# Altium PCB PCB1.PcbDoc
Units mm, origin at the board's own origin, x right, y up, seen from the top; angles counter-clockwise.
Board outline 13.84 x 13.84 mm, 2 copper layers (Top Layer, Bottom Layer); 7 components, 5 nets, 26 pads, 3 vias.
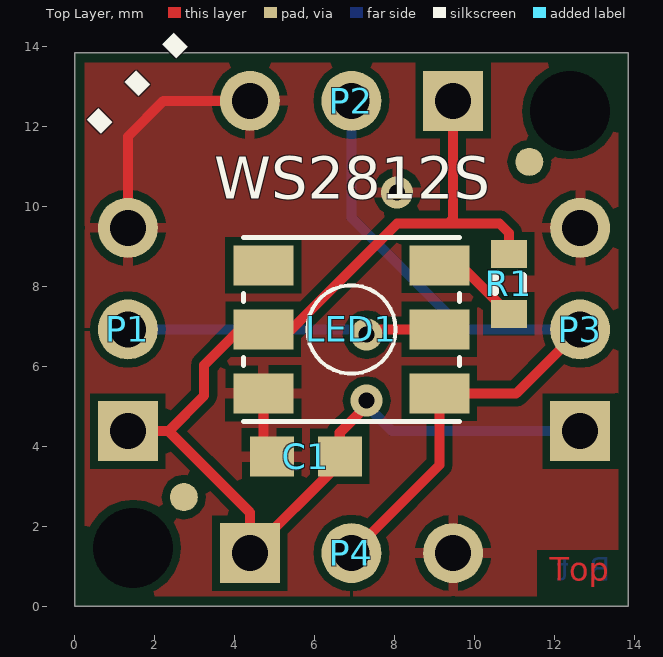
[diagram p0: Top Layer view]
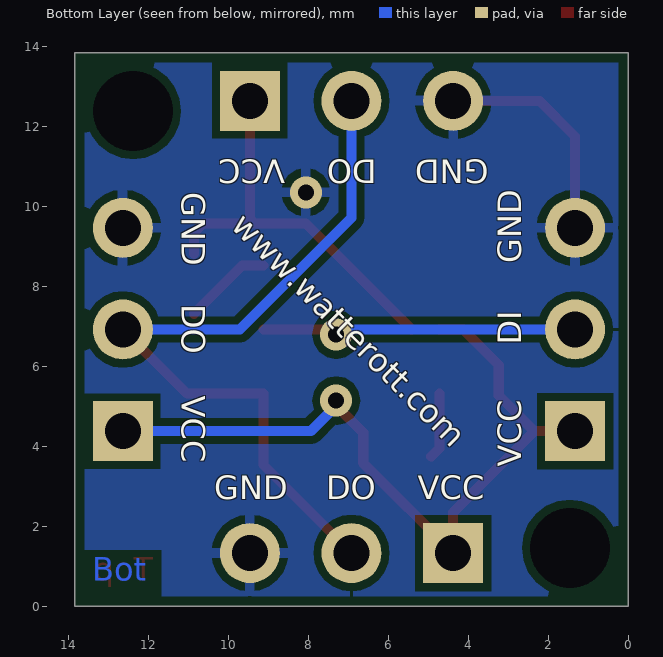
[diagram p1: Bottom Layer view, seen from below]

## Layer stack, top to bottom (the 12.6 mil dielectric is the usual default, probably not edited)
Top Layer: signal copper 0.0356
Dielectric: dielectric 0.32, FR-4, Dk 4.8
Bottom Layer: signal copper 0.0356

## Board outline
0,0 13.843,0 13.843,13.843 0,13.843

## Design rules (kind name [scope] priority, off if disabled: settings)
Clearance [All] p1: gap=0.2
PlaneClearance [All] p1: clearance=0.254
PolygonConnect [All] p1: connectstyle=Relief reliefconductorwidth=0.254 reliefentries=4 polygonreliefangle="90 Angle"
RoutingVias [All] p1: holewidth=0.8 width=1.27 viastyle="Through Hole" minholewidth=0.311 minwidth=0.3 maxholewidth=1.711 maxwidth=2.27
SilkscreenOverComponentPads [All] p1 off: minsilkscreentomaskgap=0.254
SolderMaskExpansion [All] p1: expansion=0.102
Width [All] p1: maxlimit=0.254 minlimit=0.254 preferedwidth=0.254
26 further rules are at their usual default settings.

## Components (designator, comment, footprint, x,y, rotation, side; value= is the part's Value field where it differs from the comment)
C1 "2µ2" 0603 5.779,3.746 r0 top
LED1 "WS2812S" LED_5050 6.921,6.921 r0 top
P1 "In" HDR1X3 1.333,4.381 r90 top
P2 "Out" HDR1X3 9.461,12.636 r180 top
P3 "Out" HDR1X3 12.636,4.381 r90 top
P4 "Out" HDR1X3 4.381,1.333 r0 top
R1 "150" J1-0603 10.858,8.064 r90 top

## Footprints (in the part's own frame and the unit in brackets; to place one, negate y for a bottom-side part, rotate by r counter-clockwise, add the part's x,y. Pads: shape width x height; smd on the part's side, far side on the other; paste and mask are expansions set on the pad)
0603 [mm] "Chip Capacitor; Body 1.6 x 0.8 mm (LxW typ)"
  rect 1.1x1 smd: 1(-0.85,0) 2(0.85,0)
HDR1X3 [mm] "Connector; Header; 3 Position"
  rect 1.5x1.5 hole 0.9: 1(0,0)
  round 1.5 hole 0.9: 2(2.54,0) 3(5.08,0)
J1-0603 [mm] "Chip Resistor, Body 1.6x0.8mm, IPC High Density"
  rect 0.7x0.9 smd: 1(-0.75,0) 2(0.75,0)
  silkscreen extent -0.2,-0.35 0.2,0.35, body extent -0.85,-0.48 0.85,0.48, height 0.9
LED_5050 [mm]
  rect 1.5x1 smd: 1(2.2,-1.6) 2(2.2,0) 3(2.2,1.6) 4(-2.2,1.6) 5(-2.2,0) 6(-2.2,-1.6)
  silkscreen extent -2.7,-2.3 2.7,2.3

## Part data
C1: library part C0603, "Ceramic Chip Capacitor - Standard"
P1 P2 P3 P4: library part "Header 3", "Header, 3-Pin"
R1: library part Res3, "Resistor"

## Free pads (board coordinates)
  round 0 hole 2 unplated: 0(1.46,1.46) 1(12.383,12.383)
  round 0.7 smd: 7(2.73,2.73) 8(11.367,11.112)

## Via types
v1: diameter 0.8, hole 0.4, Top Layer to Bottom Layer, 3 vias

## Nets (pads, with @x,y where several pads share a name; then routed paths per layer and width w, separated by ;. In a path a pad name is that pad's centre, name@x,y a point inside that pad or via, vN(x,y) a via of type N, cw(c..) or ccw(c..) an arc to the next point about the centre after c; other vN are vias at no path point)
GND: C1.1 LED1.6 P1.3 P2.3 P3.3 P4.3 | length 7.4
  Top Layer w0.254: P1.3 1.333,11.747 2.222,12.636 P2.3 ; LED1.6 4.721,3.954 C1.1
  other v1: 8.064,10.351
NetLED1_1: LED1.1 P2.2 P3.2 P4.2 | length 18.9
  Top Layer w0.254: P4.2 9.121,3.533 LED1.1 11.036,5.321 P3.2
  Bottom Layer w0.254: P2.2 6.921,9.716 9.716,6.921 P3.2
NetLED1_2: LED1.2 P1.2 | length 7.9
  Top Layer w0.254: v1(7.302,6.794) 7.429,6.921 LED1.2
  Bottom Layer w0.254: P1.2 7.175,6.921 v1(7.302,6.794)
NetLED1_3: LED1.3 R1.1 | length 2.2
  Top Layer w0.254: LED1.3 9.651,8.521 R1.1
VCC: C1.2 LED1.5 P1.1 P2.1 P3.1 P4.1 R1.2 | length 29.9
  Top Layer w0.254: P1.1 2.349,4.381 ; LED1.5 4.127,6.921 3.238,6.032 3.238,5.271 2.349,4.381 ; LED1.5@5.416,6.921 8.064,9.569 9.335,9.569 ; v1@7.302,5.271 7.302,5.016 6.629,4.343 C1.2 6.629,3.581 P4.1 4.381,2.349 2.349,4.381 ; P2.1 9.461,9.696 9.335,9.569 ; R1.2 10.858,9.335 10.624,9.569 9.335,9.569
  Bottom Layer w0.254: v1(7.302,5.143) 7.302,5.016 7.938,4.381 P3.1
pads on no net: LED1.4

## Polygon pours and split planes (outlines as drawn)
GND on Top Layer "GND" (solid, remove dead copper, pour order 2): 0.254,0.254 13.589,0.254 13.589,13.589 0.254,13.589
GND on Bottom Layer "GND" (solid, remove dead copper, pour order 4): 0.254,0.254 13.589,0.254 13.589,13.589 0.254,13.589

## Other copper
Top Layer:
  text "Top" at 11.874,0.445 h1
Bottom Layer:
  text "Bot" at 13.399,0.445 h1

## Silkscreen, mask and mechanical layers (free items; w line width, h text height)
Top Overlay:
  text "⋯" at 1.714,10.096 h5 r45
  text "WS2812S" at 3.492,9.842 h1.8
Bottom Overlay:
  text "GND" at 3.492,11.367 h1 r180
  text "DO" at 6.286,11.367 h1 r180
  text "VCC" at 8.572,11.367 h1 r180
  text "GND" at 11.367,10.351 h1 r90
  text "www.watterott.com" at 10.096,9.335 h1 r45
  text "GND" at 2.476,8.572 h1 r270
  text "DO" at 11.367,7.556 h1 r90
  text "DI" at 2.476,6.54 h1 r270
  text "VCC" at 11.367,5.271 h1 r90
  text "VCC" at 2.476,3.492 h1 r270
  text "VCC" at 5.271,2.476 h1
  text "DO" at 7.556,2.476 h1
  text "GND" at 10.351,2.476 h1
Mechanical 1:
  the board outline again, w0.013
